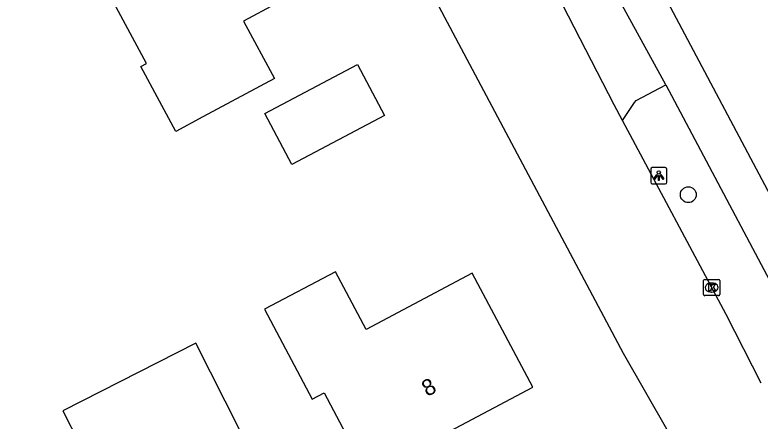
# Model space of a CAD drawing. Extents: x 162417 to 163721, y 384268 to 385416.
# Drawn here: x 163527.92 to 163573.8, y 384789.88 to 384814.9 of the extents above; entities that cross this region are included whole.
import ezdxf

# ---------------------------------------------------------------- set-up
doc = ezdxf.new("R2010")
doc.units = 0
for name, color, linetype in [('IMGEO_Boom', 7, 'Continuous'), ('IMGEO_Kolk', 7, 'Continuous'), ('IMGEO_Lichtpunt', 7, 'Continuous'), ('IMGEO_Pand', 7, 'Continuous'), ('IMGEO_Pand_nummerreeks', 7, 'Continuous'), ('IMGEO_Rijbaan_lokaal_gesloten', 7, 'Continuous'), ('IMGEO_Voetpad_open', 7, 'Continuous')]:
    doc.layers.add(name, color=color, linetype=linetype)

msp = doc.modelspace()

# ---------------------------------------------------------------- linework, layer by layer
at = {"layer": 'IMGEO_Boom'}
msp.add_circle((163569.381, 384803.827), 0.489, dxfattribs=at)
at = {"layer": 'IMGEO_Kolk'}
for p, q in [((163570.393, 384798.607), (163571.245, 384798.607)), ((163570.318, 384797.681), (163570.318, 384798.533)), ((163570.806, 384798.387), (163570.831, 384798.387)), ((163571.319, 384798.533), (163571.319, 384797.681)), ((163570.829, 384797.827), (163570.804, 384797.827)), ((163571.245, 384797.607), (163570.393, 384797.607))]:
    msp.add_line(p, q, dxfattribs=at)
for points in [[(163570.393, 384798.607), (163571.245, 384798.607)], [(163570.318, 384797.681), (163570.318, 384798.533)], [(163570.639, 384798.307), (163570.762, 384798.307), (163570.762, 384798.156), (163570.892, 384798.307), (163571.056, 384798.307), (163570.91, 384798.156), (163571.063, 384797.907), (163570.911, 384797.907), (163570.826, 384798.071), (163570.762, 384798.004), (163570.762, 384797.907), (163570.639, 384797.907), (163570.639, 384798.307)], [(163571.319, 384798.533), (163571.319, 384797.681)], [(163571.245, 384797.607), (163570.393, 384797.607)]]:
    msp.add_lwpolyline(points, dxfattribs=at)
for centre, start, end in [((163570.395, 384798.531), 91.552, 178.448), ((163570.395, 384798.531), 91.552, 178.448), ((163571.243, 384798.531), 1.552, 88.448), ((163571.243, 384798.531), 1.552, 88.448), ((163570.395, 384797.683), 181.552, 268.448), ((163570.395, 384797.683), 181.552, 268.448), ((163571.243, 384797.683), 271.552, 358.448), ((163571.243, 384797.683), 271.552, 358.448)]:
    msp.add_arc(centre, 0.0765, start, end, dxfattribs=at)
for centre, major_axis, ratio, start_param, end_param in [((163570.805, 384798.107), (-0.387, 0.002), 0.722429, 4.712389, 7.853982), ((163570.83, 384798.107), (-0.39, 0.002), 0.717154, 1.570796, 4.712389)]:
    msp.add_ellipse(centre, major_axis=major_axis, ratio=ratio, start_param=start_param, end_param=end_param, dxfattribs=at)
at = {"layer": 'IMGEO_Lichtpunt'}
for p, q in [((163567.966, 384805.494), (163567.158, 384805.494)), ((163567.966, 384805.494), (163567.158, 384805.494)), ((163567.064, 384805.399), (163567.064, 384804.592)), ((163567.064, 384805.399), (163567.064, 384804.592)), ((163568.06, 384804.592), (163568.06, 384805.399)), ((163568.06, 384804.592), (163568.06, 384805.399)), ((163567.158, 384804.498), (163567.966, 384804.498)), ((163567.158, 384804.498), (163567.966, 384804.498))]:
    msp.add_line(p, q, dxfattribs=at)
for points in [[(163567.438, 384805.063), (163567.477, 384805.035), (163567.289, 384804.773), (163567.251, 384804.8), (163567.438, 384805.063)], [(163567.54, 384805.015), (163567.587, 384805.015), (163567.587, 384804.693), (163567.54, 384804.693), (163567.54, 384805.015)], [(163567.65, 384805.035), (163567.688, 384805.062), (163567.875, 384804.8), (163567.836, 384804.772), (163567.65, 384805.035)]]:
    msp.add_lwpolyline(points, dxfattribs=at)
msp.add_circle((163567.563, 384805.197), 0.0994, dxfattribs=at)
for centre, start, end in [((163567.158, 384805.399), 90, 180), ((163567.158, 384805.399), 90, 180), ((163567.966, 384805.399), 0, 90), ((163567.966, 384805.399), 0, 90), ((163567.158, 384804.592), 180, 270), ((163567.158, 384804.592), 180, 270), ((163567.966, 384804.592), 270, 0), ((163567.966, 384804.592), 270, 360)]:
    msp.add_arc(centre, 0.0946, start, end, dxfattribs=at)
at = {"layer": 'IMGEO_Pand'}
for points in [[(163532.3, 384818.834), (163531.918, 384818.629), (163530.228, 384821.767), (163529.477, 384823.162), (163534.923, 384826.096), (163535.656, 384826.491), (163540.057, 384828.862), (163542.968, 384823.457), (163542.956, 384823.451), (163540.002, 384821.86), (163540.941, 384820.117), (163541.403, 384820.366), (163541.589, 384820.021), (163541.624, 384819.955), (163543.984, 384815.575), (163542.003, 384814.509), (163543.9, 384810.988), (163539.498, 384808.616), (163537.826, 384807.716), (163535.672, 384811.715), (163536.03, 384811.908), (163532.3, 384818.834)], [(163543.317, 384808.82), (163549.015, 384811.842), (163550.678, 384808.705), (163544.98, 384805.683), (163543.317, 384808.82)], [(163549.636, 384786.565), (163559.809, 384791.961), (163556.081, 384798.988), (163549.543, 384795.52), (163547.653, 384799.084), (163543.287, 384796.768), (163546.22, 384791.238), (163546.952, 384791.626), (163549.636, 384786.565)], [(163542.447, 384787.973), (163540.862, 384791.099), (163539.051, 384794.672), (163530.864, 384790.521), (163531.908, 384788.462), (163528.022, 384786.491), (163528.172, 384786.195), (163530.433, 384781.735), (163531.425, 384782.238), (163533.387, 384778.369), (163539.606, 384781.522), (163537.585, 384785.508), (163541.978, 384787.735)]]:
    msp.add_lwpolyline(points, dxfattribs=at)
at = {"layer": 'IMGEO_Rijbaan_lokaal_gesloten'}
for points in [[(163498.731, 384918.106), (163500, 384915.752), (163550.928, 384821.281), (163565.372, 384794.06), (163568.118, 384789.259)], [(163565.334, 384808.395), (163564.821, 384809.357), (163560.255, 384818.233)], [(163573.858, 384792.219), (163571.704, 384796.445), (163565.334, 384808.395)]]:
    msp.add_lwpolyline(points, dxfattribs=at)
at = {"layer": 'IMGEO_Voetpad_open'}
for points in [[(163579.211, 384794.807), (163552.107, 384845.87), (163518.056, 384909.494), (163515.928, 384908.35), (163515.734, 384908.25)], [(163567.994, 384810.595), (163562.999, 384819.749)], [(163565.334, 384808.395), (163566.069, 384809.515), (163566.174, 384809.627), (163567.994, 384810.595)], [(163567.994, 384810.595), (163576.893, 384793.832)]]:
    msp.add_lwpolyline(points, dxfattribs=at)

# ---------------------------------------------------------------- texts
at = {"layer": 'IMGEO_Pand_nummerreeks'}
msp.add_text('8', height=1, rotation=27.9425, dxfattribs=at).set_placement((163553.303, 384791.362))

doc.saveas('drawing.dxf')
